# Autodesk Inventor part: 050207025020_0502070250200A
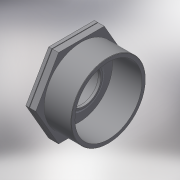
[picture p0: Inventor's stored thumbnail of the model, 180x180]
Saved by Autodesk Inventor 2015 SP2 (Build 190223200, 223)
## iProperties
Created: 2017-05
Part Number: 050207025020_0502070250200A
Material: Generic
Description: PLASSON REDUCING BUSHING 2.1/2"-2"
Document SubType Name: Modeling
Designer: KIM
Density: 1 g/cm^3
Appearance: Default
Author: KIM
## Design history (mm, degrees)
derived "050207.ipt"
feature "Solid1::050207.ipt"
tag "TaggingFeature1"
body "Solid1"
other parameters: "d1" = 72.226, "d5" = 29, "d8" = 0.44, "d12" = 0, "d15" = 44, "d19" = 0, "d30" = 9.77778, "d31" = 4.88889, "d33" = 56.656, "d34" = 65.0034, "d36" = 4, "d37" = 62.3216, "d38" = 29.04, "d39" = 50.9904, "d40" = 2.9, "d41" = 0, "H_" = 44, "R_" = 72.226, "l_2" = 29, "Rp_" = 56.656
